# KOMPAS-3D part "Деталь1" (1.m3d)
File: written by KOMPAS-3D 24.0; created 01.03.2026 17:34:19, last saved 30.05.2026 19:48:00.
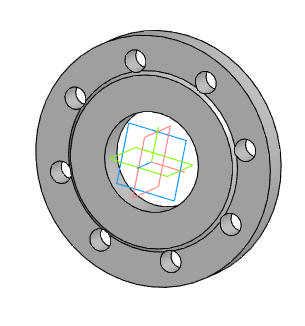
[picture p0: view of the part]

Document properties: Автор: R2D2; Полное имя файла: E:\Работа\Зайцев\GVWR3131M-2W-F-S Задвижка клиновая с выдвижным штоком DN.ru Ду50-100 Ру40\исходные материалы\DN80\1.m3d

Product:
- Part/product: Деталь1
    Масса: 4.236703
    additional columns: Типовые

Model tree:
1. Эскиз:2
2. Элемент вращения:1
     Угол 1 = 360
3. Эскиз:3  (with: Грань.Элемент вращения:1)
4. Элемент выдавливания:2
     Расстояние 1 = 3; Расстояние 2 = 21
5. Массив по концентрической сетке:1  (with: Элемент выдавливания:2, Эскиз:3, Грань.Элемент вращения:1)  (8 pattern instances)
     Шаг 2 = 360
6. Эскиз:4  (with: Грань.Элемент вращения:1)
7. Элемент выдавливания:3
     Расстояние 2 = 2.5

Expressions: 138+6
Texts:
  Линейный размер с обрывом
